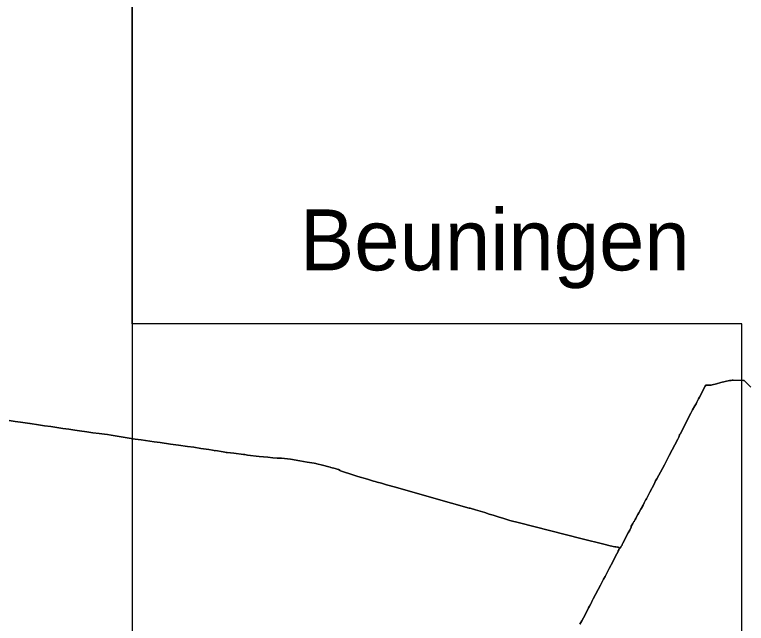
# Model space of a CAD drawing. Extents: x 113371 to 291721, y 393993 to 520143.
# Drawn here: x 176035 to 182036, y 426544 to 431534 of the extents above; entities that cross this region are included whole.
import ezdxf

# ---------------------------------------------------------------- set-up
doc = ezdxf.new("R2010")
doc.units = 0
for name, color, linetype in [('Boudingbox', 7, 'Continuous'), ('Default', 7, 'Continuous'), ('plaatsnamen', 7, 'Continuous')]:
    doc.layers.add(name, color=color, linetype=linetype)

msp = doc.modelspace()

# ---------------------------------------------------------------- linework, layer by layer
at = {"layer": 'Boudingbox'}
for p, q in [((177000, 435500), (177000, 420000)), ((177000, 428999.18229), (177000, 435000)), ((182000, 428999.18229), (177000, 428999.18229)), ((182000, 425500), (182000, 428999.18229))]:
    msp.add_line(p, q, dxfattribs=at)
at = {"layer": 'Default'}
for points in [[(182072.705625, 428481.0625), (182035.195625, 428517.7525), (182017.895625, 428533.7225), (182015.345625, 428535.3425), (182013.965625, 428535.8825), (182011.985625, 428536.2425), (181928.715625, 428537.3825), (181919.055625, 428536.9925), (181910.985625, 428536.0925), (181903.005625, 428534.7425), (181898.335625, 428533.6725), (181827.275625, 428517.5825), (181792.025625, 428508.8025), (181756.785625, 428500.0225), (181746.415625, 428498.0625), (181740.235625, 428497.3125), (181723.495625, 428496.3325), (181703.235625, 428496.2825), (181698.895625, 428488.0625), (181651.355625, 428397.8625), (181644.105625, 428384.1125), (181631.165625, 428358.4125), (181624.645625, 428344.6925), (181612.855625, 428327.2525), (181595.115625, 428293.5225), (181581.735625, 428266.1125), (181493.085625, 428096.3125), (181489.245625, 428091.3925), (181487.355625, 428086.1225), (181482.375625, 428069.3325), (181474.125625, 428053.6425), (181403.695625, 427919.2625), (181382.375625, 427877.6825), (181365.445625, 427844.8625), (181348.495625, 427813.3525), (181302.975625, 427727.8425), (181292.405625, 427711.7225), (181278.925625, 427685.3925)], [(181723.495625, 428496.3325), (181740.235625, 428497.3125), (181746.415625, 428498.0625), (181756.785625, 428500.0225), (181792.025625, 428508.8025), (181827.275625, 428517.5825), (181898.335625, 428533.6725), (181903.005625, 428534.7425), (181910.985625, 428536.0925), (181919.055625, 428536.9925), (181928.715625, 428537.3825), (182011.985625, 428536.2425), (182013.965625, 428535.8825), (182015.345625, 428535.3425), (182017.895625, 428533.7225), (182035.195625, 428517.7525), (182072.705625, 428481.0625)], [(181125.465625, 427395.8025), (181129.745625, 427403.4925), (181130.585625, 427405.0525), (181147.225625, 427436.2625), (181155.305625, 427450.4525), (181171.325625, 427479.8625), (181176.445625, 427489.4825), (181183.555625, 427502.8125), (181184.735625, 427505.0325), (181189.485625, 427514.0125), (181199.025625, 427533.4425), (181209.595625, 427552.6625), (181211.985625, 427557.0725), (181216.735625, 427565.8725), (181228.115625, 427586.9325), (181244.655625, 427618.9825), (181278.925625, 427685.3925), (181292.405625, 427711.7225), (181302.975625, 427727.8425), (181348.495625, 427813.3525), (181365.445625, 427844.8625), (181382.375625, 427877.6825), (181403.695625, 427919.2625), (181474.125625, 428053.6425), (181482.375625, 428069.3325), (181487.355625, 428086.1225), (181489.245625, 428091.3925), (181493.085625, 428096.3125), (181581.735625, 428266.1125), (181595.115625, 428293.5225), (181612.855625, 428327.2525), (181624.645625, 428344.6925), (181631.165625, 428358.4125), (181644.105625, 428384.1125), (181651.355625, 428397.8625), (181698.895625, 428488.0625), (181703.235625, 428496.2825), (181723.495625, 428496.3325)], [(175989.695625, 428207.4725), (176039.405625, 428199.2725), (176084.695625, 428192.2825), (176159.645625, 428183.7525), (176162.815625, 428183.3125), (176231.755625, 428171.2225), (176281.555625, 428163.9525), (176330.985625, 428156.9025), (176380.665625, 428149.5425), (176430.355625, 428141.9425), (176479.705625, 428134.6925), (176529.295625, 428127.7625), (176566.285625, 428122.3825), (176628.145625, 428113.0425), (176677.815625, 428106.8725), (176727.705625, 428100.8225), (176771.205625, 428095.3525), (176796.665625, 428091.8125), (176826.285625, 428087.0125), (176875.995625, 428078.4725), (176925.035625, 428070.6525), (176974.495625, 428062.8225), (177024.505625, 428055.2725), (177074.225625, 428049.1425), (177108.705625, 428042.8125), (177179.195625, 428031.1525), (177180.625625, 428033.0425)], [(177583.915625, 427973.5825), (177562.315625, 427977.4925), (177505.575625, 427987.3325), (177454.075625, 427994.2425), (177380.165625, 428004.8425), (177314.035625, 428014.1325), (177228.785625, 428026.1325), (177180.625625, 428033.0425), (177179.195625, 428031.1525), (177108.705625, 428042.8125), (177074.225625, 428049.1425), (177024.505625, 428055.2725), (176974.495625, 428062.8225), (176925.035625, 428070.6525), (176875.995625, 428078.4725), (176826.285625, 428087.0125), (176796.665625, 428091.8125), (176771.205625, 428095.3525), (176727.705625, 428100.8225), (176677.815625, 428106.8725), (176628.145625, 428113.0425), (176566.285625, 428122.3825), (176529.295625, 428127.7625), (176479.705625, 428134.6925), (176430.355625, 428141.9425), (176380.665625, 428149.5425), (176330.985625, 428156.9025), (176281.555625, 428163.9525), (176231.755625, 428171.2225), (176162.815625, 428183.3125), (176159.645625, 428183.7525), (176084.695625, 428192.2825), (176039.405625, 428199.2725), (175989.695625, 428207.4725)], [(177180.625625, 428033.0425), (177228.785625, 428026.1325), (177314.035625, 428014.1325), (177380.165625, 428004.8425), (177454.075625, 427994.2425), (177505.575625, 427987.3325), (177562.315625, 427977.4925), (177583.915625, 427973.5825), (177627.935625, 427969.4725), (177657.405625, 427964.0225), (177671.055625, 427961.8525), (177678.225625, 427959.4025), (177683.285625, 427960.8825), (177746.255625, 427950.4825), (177759.785625, 427948.3325), (177769.655625, 427945.9025), (177778.485625, 427944.4025), (177831.675625, 427938.1325), (177912.285625, 427927.5825), (177916.065625, 427927.6825), (177921.095625, 427927.7225), (177924.465625, 427927.5925), (177945.915625, 427924.2125), (178041.545625, 427913.1325), (178110.815625, 427906.2425), (178153.295625, 427901.9425), (178189.055625, 427898.9525), (178225.215625, 427897.1825), (178297.545625, 427888.8925), (178373.455625, 427876.2025), (178434.615625, 427866.1625), (178491.515625, 427856.0125), (178505.115625, 427853.4725), (178512.625625, 427851.4925), (178560.455625, 427840.0125), (178610.825625, 427827.3425), (178622.545625, 427824.3225), (178627.245625, 427823.1125)], [(178783.355625, 427770.0225), (178740.745625, 427784.1725), (178708.735625, 427795.3125), (178704.795625, 427797.1125), (178692.425625, 427804.0225), (178688.575625, 427805.3625), (178663.165625, 427813.1025), (178627.245625, 427823.1125), (178622.545625, 427824.3225), (178610.825625, 427827.3425), (178560.455625, 427840.0125), (178512.625625, 427851.4925), (178505.115625, 427853.4725), (178491.515625, 427856.0125), (178434.615625, 427866.1625), (178373.455625, 427876.2025), (178297.545625, 427888.8925), (178225.215625, 427897.1825), (178189.055625, 427898.9525), (178153.295625, 427901.9425), (178110.815625, 427906.2425), (178041.545625, 427913.1325), (177945.915625, 427924.2125), (177924.465625, 427927.5925), (177921.095625, 427927.7225), (177916.065625, 427927.6825), (177912.285625, 427927.5825), (177831.675625, 427938.1325), (177778.485625, 427944.4025), (177769.655625, 427945.9025), (177759.785625, 427948.3325), (177746.255625, 427950.4825), (177683.285625, 427960.8825), (177678.225625, 427959.4025), (177671.055625, 427961.8525), (177657.405625, 427964.0225), (177627.935625, 427969.4725), (177583.915625, 427973.5825)], [(178627.245625, 427823.1125), (178663.165625, 427813.1025), (178688.575625, 427805.3625), (178692.425625, 427804.0225), (178704.795625, 427797.1125), (178708.735625, 427795.3125), (178740.745625, 427784.1725), (178783.355625, 427770.0225), (178834.275625, 427754.3025), (178849.915625, 427749.1725), (178928.405625, 427725.3825), (178978.285625, 427711.0125), (178991.375625, 427707.3625), (179009.695625, 427702.6925), (179042.735625, 427693.1625), (179086.065625, 427680.6625), (179159.525625, 427659.5425), (179473.995625, 427569.4425), (179761.805625, 427489.1425)], [(180964.155625, 427094.7625), (180984.205625, 427133.8025), (180986.275625, 427137.7425), (180992.145625, 427148.9525), (180989.875625, 427148.5125), (180996.825625, 427162.4125), (180992.705625, 427164.6325), (180984.485625, 427167.7725), (180981.955625, 427168.3825), (180979.025625, 427168.9225), (180966.595625, 427170.3325), (180956.605625, 427172.0125), (180944.735625, 427174.4725), (180907.965625, 427183.3625), (180879.085625, 427190.5525), (180679.705625, 427241.0425), (180174.745625, 427369.3425), (180096.525625, 427388.2125), (180037.905625, 427406.3125), (180010.045625, 427415.8025), (179958.495625, 427430.8225), (179927.855625, 427440.4725), (179890.525625, 427451.5725), (179854.555625, 427462.5525), (179815.305625, 427474.1725), (179771.055625, 427487.0125), (179761.805625, 427489.1425), (179473.995625, 427569.4425), (179159.525625, 427659.5425), (179086.065625, 427680.6625), (179042.735625, 427693.1625), (179009.695625, 427702.6925), (178991.375625, 427707.3625), (178978.285625, 427711.0125), (178928.405625, 427725.3825), (178849.915625, 427749.1725), (178834.275625, 427754.3025), (178783.355625, 427770.0225)], [(181278.925625, 427685.3925), (181244.655625, 427618.9825), (181228.115625, 427586.9325), (181216.735625, 427565.8725), (181211.985625, 427557.0725), (181209.595625, 427552.6625), (181199.025625, 427533.4425), (181189.485625, 427514.0125), (181184.735625, 427505.0325), (181183.555625, 427502.8125), (181176.445625, 427489.4825), (181171.325625, 427479.8625), (181155.305625, 427450.4525), (181147.225625, 427436.2625), (181130.585625, 427405.0525), (181129.745625, 427403.4925), (181125.465625, 427395.8025), (181116.075625, 427378.1325), (181115.165625, 427376.4325), (181112.765625, 427377.7625), (181104.075625, 427361.5725), (181089.435625, 427334.3025), (181092.465625, 427332.6425), (181079.515625, 427307.8725), (181067.875625, 427285.6025), (181023.005625, 427201.3125), (181023.715625, 427200.3825), (181018.985625, 427189.9525), (181016.615625, 427185.0125), (181014.005625, 427181.2325), (181012.915625, 427179.6525), (181000.785625, 427160.2625), (180996.825625, 427162.4125), (180989.875625, 427148.5125), (180992.145625, 427148.9525), (180986.275625, 427137.7425), (180984.205625, 427133.8025), (180964.155625, 427094.7625)], [(179761.805625, 427489.1425), (179771.055625, 427487.0125), (179815.305625, 427474.1725), (179854.555625, 427462.5525), (179890.525625, 427451.5725), (179927.855625, 427440.4725), (179958.495625, 427430.8225), (180010.045625, 427415.8025), (180037.905625, 427406.3125), (180096.525625, 427388.2125), (180174.745625, 427369.3425), (180679.705625, 427241.0425), (180879.085625, 427190.5525), (180907.965625, 427183.3625), (180944.735625, 427174.4725), (180956.605625, 427172.0125), (180966.595625, 427170.3325), (180979.025625, 427168.9225), (180981.955625, 427168.3825), (180984.485625, 427167.7725), (180992.705625, 427164.6325), (180996.825625, 427162.4125), (181000.785625, 427160.2625), (181012.915625, 427179.6525), (181014.005625, 427181.2325), (181016.615625, 427185.0125), (181018.985625, 427189.9525), (181023.715625, 427200.3825), (181023.005625, 427201.3125), (181067.875625, 427285.6025), (181079.515625, 427307.8725), (181092.465625, 427332.6425), (181089.435625, 427334.3025), (181104.075625, 427361.5725), (181112.765625, 427377.7625), (181115.165625, 427376.4325), (181116.075625, 427378.1325), (181125.465625, 427395.8025)], [(180671.555625, 426536.6525), (180686.665625, 426564.0625), (180700.855625, 426589.8225), (180702.295625, 426592.5925), (180742.565625, 426670.3225), (180749.875625, 426684.2825), (180749.965625, 426684.4725), (180760.575625, 426705.0225), (180766.145625, 426715.0625), (180769.825625, 426724.4325), (180780.815625, 426744.8925), (180839.565625, 426857.4325), (180856.605625, 426890.5025), (180865.765625, 426907.5925), (180877.015625, 426928.3725), (180911.745625, 426993.6325), (180940.665625, 427049.0225), (180964.155625, 427094.7625)], [(180964.155625, 427094.7625), (180940.665625, 427049.0225), (180911.745625, 426993.6325), (180877.015625, 426928.3725), (180865.765625, 426907.5925), (180856.605625, 426890.5025), (180839.565625, 426857.4325), (180780.815625, 426744.8925), (180769.825625, 426724.4325), (180766.145625, 426715.0625), (180760.575625, 426705.0225), (180749.965625, 426684.4725), (180749.875625, 426684.2825), (180742.565625, 426670.3225), (180702.295625, 426592.5925), (180700.855625, 426589.8225), (180686.665625, 426564.0625), (180671.555625, 426536.6525)]]:
    msp.add_lwpolyline(points, dxfattribs=at)

# ---------------------------------------------------------------- texts
at = {"layer": 'plaatsnamen'}
msp.add_text('Beuningen', height=500, dxfattribs=at).set_placement((178374.384494, 429437.83414))

doc.saveas('drawing.dxf')
